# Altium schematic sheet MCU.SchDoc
size A3; CompanyName: Icoteq Ltd; Address1: Cambridge House; Address2: 1 Henry Street; Address3: Bath; Address4: BA1 1BT; DocumentNumber: MCU & Bluetooth; SheetNumber: 2
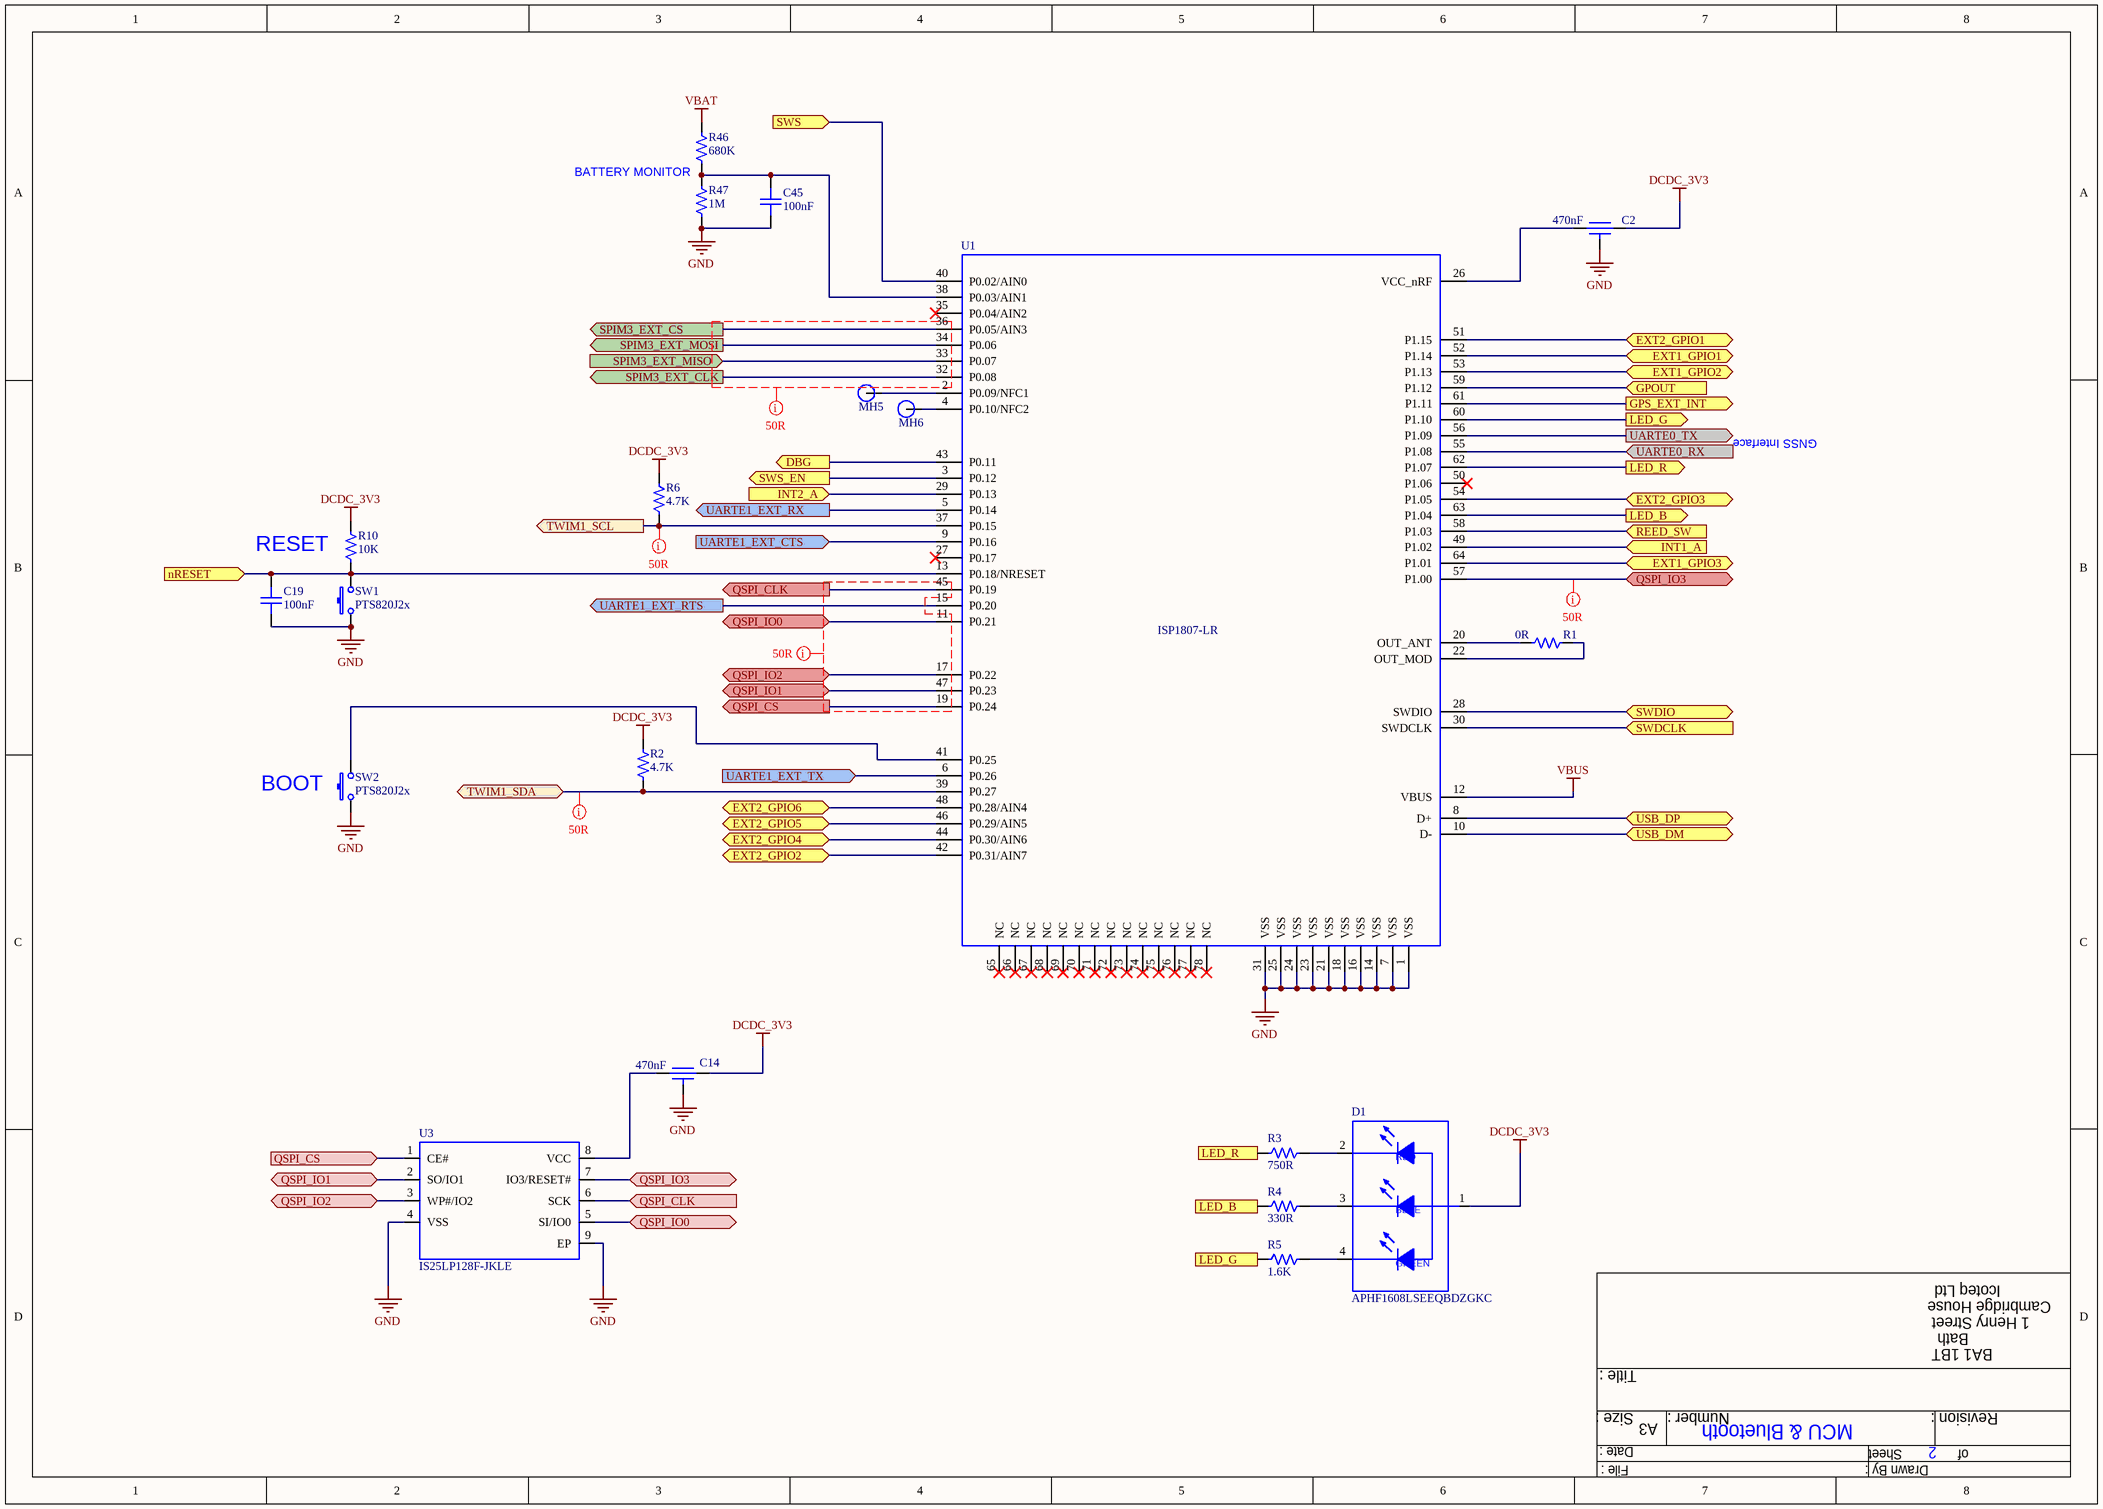
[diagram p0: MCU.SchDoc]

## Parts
C2  value 470nF  [YFF15PC]  (hidden comment: 470NF 0402 6.3V +50%/-20%)
C14  value 470nF  [YFF15PC]  (hidden comment: 470NF 0402 6.3V +50%/-20%)
C19  value 100nF  [CAP0201L]  (hidden comment: 100NF 0201 35V 10% X5R)
C45  value 100nF  [CAP0201L]  (hidden comment: 100NF 0201 35V 10% X5R)
D1  APHF1608LSEEQBDZGKC  [LED RGB 0603]
MH5  Mounting Hole 0.5mm  [Mounting Hole 0.5mm]  (value not drawn)
MH6  Mounting Hole 0.5mm  [Mounting Hole 0.5mm]  (value not drawn)
R1  value 0R  [RES0201N]  (hidden comment: 0R 0201)
R2  value 4.7K  [RES0201L]  (hidden comment: 4.7K 0201 1% 100PPM)
R3  value 750R  [RES0201L]  (hidden comment: 750R 0201 1% 100PPM)
R4  value 330R  [RES0201L]  (hidden comment: 330R 0201 1% 100PPM)
R5  value 1.6K  [RES0201L]  (hidden comment: 1.6K 0201 1% 100PPM)
R6  value 4.7K  [RES0201L]  (hidden comment: 4.7K 0201 1% 100PPM)
R10  value 10K  [RES0201L]  (hidden comment: 10K 0201 1% 100PPM)
R46  value 680K  [RES0402N]  (hidden comment: 680K 0402 1%)
R47  value 1M  [RES0402N]  (hidden comment: 1M 0402 1%)
SW1  PTS820J2x  [TL1015]
SW2  PTS820J2x  [TL1015]
U1  ISP1807-LR  [ISP1807-LR]
U3  IS25LP128F-JKLE  [SON127P600X80_HS-9N]

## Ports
DBG (out), EXT1_GPIO1 (bidir), EXT1_GPIO2 (bidir), EXT1_GPIO3 (bidir), EXT2_GPIO1 (bidir), EXT2_GPIO2 (bidir), EXT2_GPIO3 (bidir), EXT2_GPIO4 (bidir), EXT2_GPIO5 (bidir), EXT2_GPIO6 (bidir), GPOUT (in), GPS_EXT_INT (out), INT1_A (in), INT2_A (in), LED_B (in), LED_B (out), LED_G (in), LED_G (out), LED_R (in), LED_R (out), nRESET (in), QSPI_CLK (in), QSPI_CLK (out), QSPI_CS (in), QSPI_CS (out), QSPI_IO0 (bidir), QSPI_IO1 (bidir), QSPI_IO2 (bidir), QSPI_IO3 (bidir), REED_SW (in), SPIM3_EXT_CLK (out), SPIM3_EXT_CS (out), SPIM3_EXT_MISO (in), SPIM3_EXT_MOSI (out), SWDCLK (in), SWDIO (bidir), SWS (in), SWS_EN (out), TWIM1_SCL (out), TWIM1_SDA (bidir), UARTE0_RX (in), UARTE0_TX (out), UARTE1_EXT_CTS (in), UARTE1_EXT_RTS (out), UARTE1_EXT_RX (out), UARTE1_EXT_TX (in), USB_DM (bidir), USB_DP (bidir)

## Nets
DCDC_3V3: C2.1 C14.1 D1.1 R2.2 R6.2 R10.2
GND: C2.3 C14.3 C19.1 C45.1 R47.1 SW1.1 SW1.G1 SW1.G2 SW1.G3 SW1.G4 SW2.1 SW2.G1 SW2.G2 SW2.G3 SW2.G4 U1.1(VSS) U1.7(VSS) U1.14(VSS) U1.16(VSS) U1.18(VSS) U1.21(VSS) U1.23(VSS) U1.24(VSS) U1.25(VSS) U1.31(VSS) U3.4(VSS) U3.9(EP)
VBAT: R46.2
VBUS: U1.12(VBUS)
DBG: U1.43(P0.11) ; port DBG
EXT1_GPIO1: U1.52(P1.14) ; port EXT1_GPIO1
EXT1_GPIO2: U1.53(P1.13) ; port EXT1_GPIO2
EXT1_GPIO3: U1.64(P1.01) ; port EXT1_GPIO3
EXT2_GPIO1: U1.51(P1.15) ; port EXT2_GPIO1
EXT2_GPIO2: U1.42(P0.31/AIN7) ; port EXT2_GPIO2
EXT2_GPIO3: U1.54(P1.05) ; port EXT2_GPIO3
EXT2_GPIO4: U1.44(P0.30/AIN6) ; port EXT2_GPIO4
EXT2_GPIO5: U1.46(P0.29/AIN5) ; port EXT2_GPIO5
EXT2_GPIO6: U1.48(P0.28/AIN4) ; port EXT2_GPIO6
GPOUT: U1.59(P1.12) ; port GPOUT
GPS_EXT_INT: U1.61(P1.11) ; port GPS_EXT_INT
INT1_A: U1.49(P1.02) ; port INT1_A
INT2_A: U1.29(P0.13) ; port INT2_A
LED_B: R4.1 U1.63(P1.04) ; port LED_B
LED_G: R5.1 U1.60(P1.10) ; port LED_G
LED_R: R3.1 U1.62(P1.07) ; port LED_R
nRESET: C19.2 R10.1 SW1.2 U1.13(P0.18/NRESET) ; port nRESET
QSPI_CLK: U1.45(P0.19) U3.6(SCK) ; port QSPI_CLK
QSPI_CS: U1.19(P0.24) U3.1(CE#) ; port QSPI_CS
QSPI_IO0: U1.11(P0.21) U3.5(SI/IO0) ; port QSPI_IO0
QSPI_IO1: U1.47(P0.23) U3.2(SO/IO1) ; port QSPI_IO1
QSPI_IO2: U1.17(P0.22) U3.3(WP#/IO2) ; port QSPI_IO2
QSPI_IO3: U1.57(P1.00) U3.7(IO3/RESET#) ; port QSPI_IO3
REED_SW: U1.58(P1.03) ; port REED_SW
SPIM3_EXT_CLK: U1.32(P0.08) ; port SPIM3_EXT_CLK
SPIM3_EXT_CS: U1.36(P0.05/AIN3) ; port SPIM3_EXT_CS
SPIM3_EXT_MISO: U1.33(P0.07) ; port SPIM3_EXT_MISO
SPIM3_EXT_MOSI: U1.34(P0.06) ; port SPIM3_EXT_MOSI
SWDCLK: U1.30(SWDCLK) ; port SWDCLK
SWDIO: U1.28(SWDIO) ; port SWDIO
SWS: U1.40(P0.02/AIN0) ; port SWS
SWS_EN: U1.3(P0.12) ; port SWS_EN
TWIM1_SCL: R6.1 U1.37(P0.15) ; port TWIM1_SCL
TWIM1_SDA: R2.1 U1.39(P0.27) ; port TWIM1_SDA
UARTE0_RX: U1.55(P1.08) ; port UARTE0_RX
UARTE0_TX: U1.56(P1.09) ; port UARTE0_TX
UARTE1_EXT_CTS: U1.9(P0.16) ; port UARTE1_EXT_CTS
UARTE1_EXT_RTS: U1.15(P0.20) ; port UARTE1_EXT_RTS
UARTE1_EXT_RX: U1.5(P0.14) ; port UARTE1_EXT_RX
UARTE1_EXT_TX: U1.6(P0.26) ; port UARTE1_EXT_TX
USB_DM: U1.10(D-) ; port USB_DM
USB_DP: U1.8(D+) ; port USB_DP
NetC2_2: C2.2 U1.26(VCC_nRF)
NetC14_2: C14.2 U3.8(VCC)
NetC45_2: C45.2 R46.1 R47.2 U1.38(P0.03/AIN1)
NetD1_2: D1.2 R3.2
NetD1_3: D1.3 R4.2
NetD1_4: D1.4 R5.2
NetMH5_1: MH5.1 U1.2(P0.09/NFC1)
NetMH6_1: MH6.1 U1.4(P0.10/NFC2)
NetR1_1: R1.1 U1.20(OUT_ANT)
NetR1_2: R1.2 U1.22(OUT_MOD)
NetSW2_2: SW2.2 U1.41(P0.25)

Not connected (* = marked no-connect by the designer): U1 27(P0.17)* 35(P0.04/AIN2)* 50(P1.06)* 65(NC)* 66(NC)* 67(NC)* 68(NC)* 69(NC)* 70(NC)* 71(NC)* 72(NC)* 73(NC)* 74(NC)* 75(NC)* 76(NC)* 77(NC)* 78(NC)*

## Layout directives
net class 50R_track: (no net found under the mark), QSPI_IO3, TWIM1_SCL, TWIM1_SDA

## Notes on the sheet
- BATTERY MONITOR
- GNSS Interface
- RESET
- (near SW2) BOOT

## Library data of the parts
C2 C14 = CAP FEEDTHRU 470NF 0402 6.3V +50%/-20%: Manufacturer: TDK; Manufacturers Part Number: YFF15PC0J474M
C19 C45 = CAP CER 100NF 0201 35V 10% X5R: Manufacturer: Murata; Manufacturers Part Number: GRM033R6YA104KE14D
D1 = LED RGB 0603 2MA: Manufacturer: Kingbright
MH5 MH6 = Mounting Hole 0.5mm: Manufacturer: NOT FITTED PART
R1 = RES 0R 0201
R2 R6 = RES 4.7K 0201 1% 100PPM: PPM: 100
R3 = RES 750R 0201 1% 100PPM: PPM: 100
R4 = RES 330R 0201 1% 100PPM: PPM: 100
R5 = RES 1.6K 0201 1% 100PPM: PPM: 100
R10 = RES 10K 0201 1% 100PPM: PPM: 100
R46 = RES 680K 0402 1% 100PPM: PPM: 100
R47 = RES 1M 0402 1% 100PPM: PPM: 100
SW1 SW2 = PTS820J2x: SW SPST PB 50MA 12V SMT CK variant; Manufacturer: C&K; Manufacturers Part Number: PTS820J2xM SMTR LFS
U1 = ISP1807-LR: IC ISP Smart Bluetooth Module; Manufacturer: InsightSIP; Manufacturers Part Number: ISP1807-LR-ST
U3 = IS25LP128F-JKLE: IC MEM SERIAL NOR FLASH QSPI 128Mb/16MB 3.6V 166MHz WSON8 6X5; Manufacturer: ISSI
